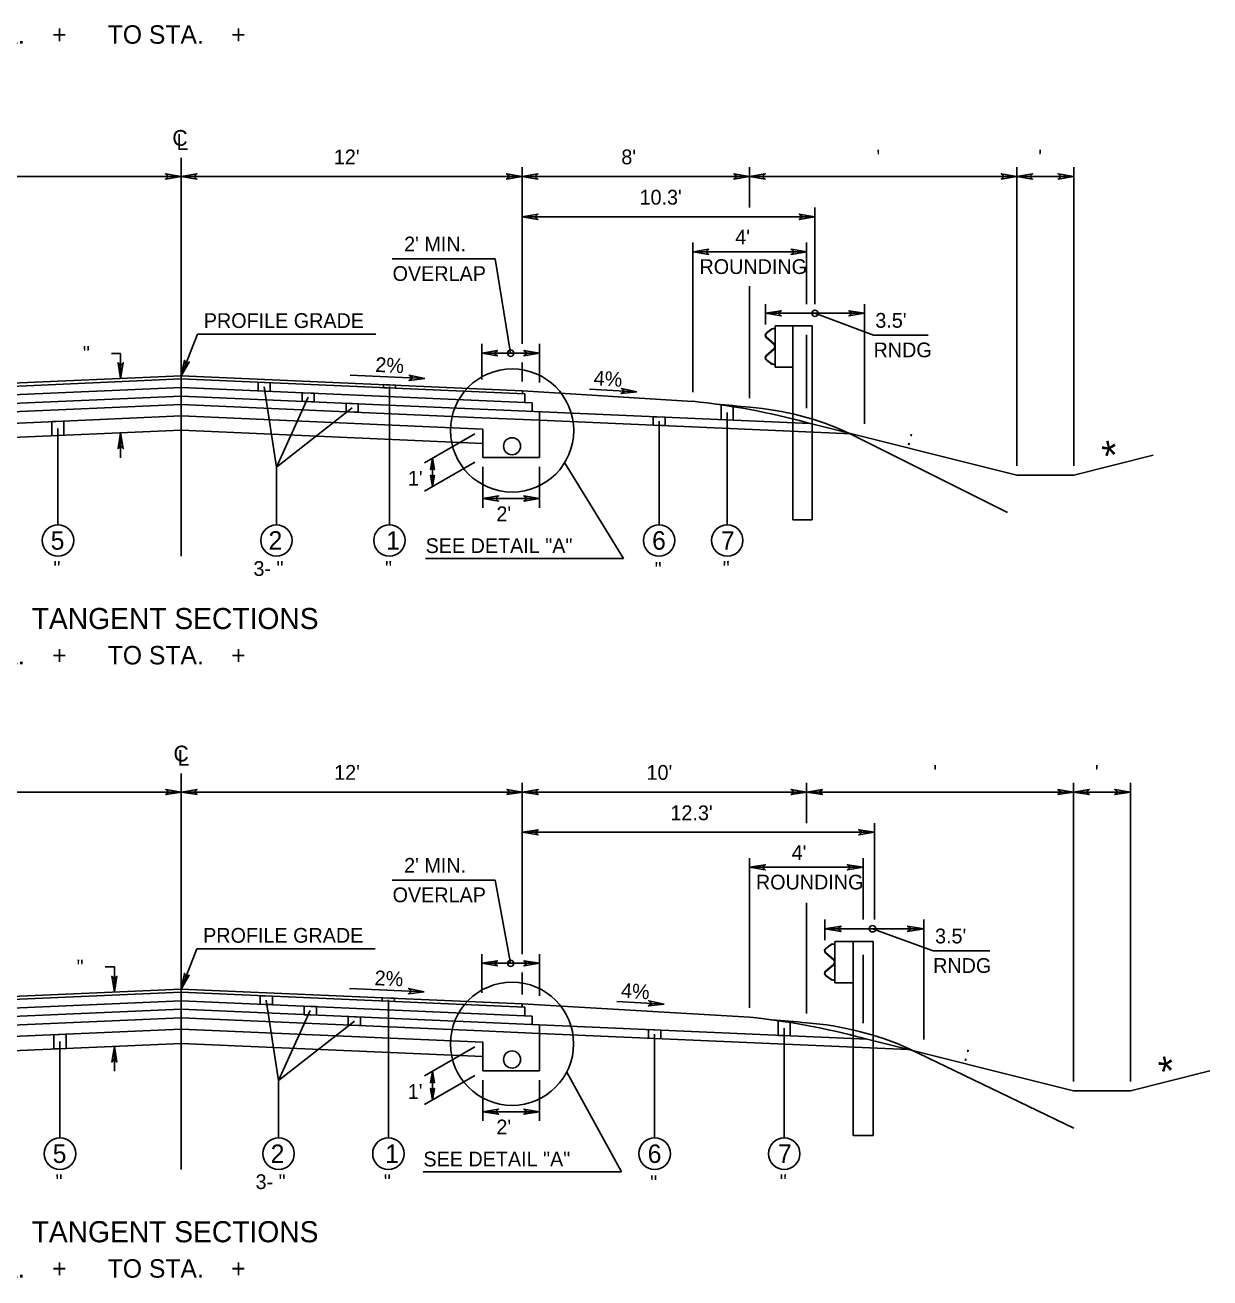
# Model space of a CAD drawing. Extents: x -540 to 1231, y -564 to 421.
# Drawn here: x 268.9 to 381.2, y 58.8 to 177.6 of the extents above; entities that cross this region are included whole.
import ezdxf

# ---------------------------------------------------------------- set-up
doc = ezdxf.new("R2010")
doc.units = 0
doc.layers.add('1', color=7, linetype='Continuous')
doc.layers.add('Des_ Drain_ Ftrs', color=7, linetype='Continuous')

msp = doc.modelspace()

# ---------------------------------------------------------------- linework, layer by layer
at = {"layer": '1'}
for p, q in [((283.71, 127.24), (283.71, 165)), ((316.04, 147.36), (316.04, 164.12)), ((337.59, 160.3), (337.59, 164.12)), ((362.93, 135.79), (362.93, 164.12)), ((368.32, 135.79), (368.32, 164.12)), ((283.71, 163.24), (251.38, 163.24)), ((283.71, 163.24), (316.04, 163.24)), ((316.04, 163.24), (337.59, 163.24)), ((337.59, 163.24), (362.93, 163.24)), ((362.93, 163.24), (368.32, 163.24)), ((316.04, 159.42), (343.79, 159.42)), ((343.79, 151.14), (343.79, 160.3)), ((332.21, 142.79), (332.21, 156.97)), ((342.98, 151.14), (342.98, 156.97)), ((332.23, 156.09), (343.01, 156.09)), ((303.72, 155.43), (313.48, 155.43)), ((314.94, 146.48), (313.48, 155.43)), ((337.59, 142.23), (337.59, 152.82)), ((339.1, 149.19), (339.1, 151.14)), ((348.48, 139.78), (348.48, 151.14)), ((339.1, 150.26), (348.48, 150.26)), ((343.79, 150.26), (349.35, 148.19)), ((339.7, 148.8), (339.18, 148.41)), ((339.71, 148.77), (339.2, 148.38)), ((340.01, 148.85), (339.7, 148.8)), ((340.01, 148.82), (339.71, 148.77)), ((340.01, 149.08), (340.01, 145.15)), ((340.01, 149.08), (341.7, 149.08)), ((341.7, 149.08), (341.7, 130.68)), ((343.52, 149.08), (341.7, 149.08)), ((343.52, 149.08), (343.52, 130.68)), ((283.71, 144.34), (285.24, 148.29)), ((302.15, 148.29), (285.24, 148.29)), ((312.2, 143.97), (312.2, 147.36)), ((317.68, 143.7), (317.68, 147.36)), ((339.17, 147.97), (339.9, 147.34)), ((339.19, 148), (339.92, 147.36)), ((342.98, 141.27), (342.98, 148.22)), ((349.35, 148.19), (354.51, 148.19)), ((277.97, 146.45), (277.09, 146.45)), ((277.97, 146.45), (277.97, 144.09)), ((312.2, 146.48), (317.68, 146.48)), ((339.9, 146.89), (339.17, 146.25)), ((339.92, 146.87), (339.19, 146.23)), ((339.98, 147.15), (339.98, 147.08)), ((340.01, 147.15), (340.01, 147.08)), ((316.04, 143.8), (316.04, 145.6)), ((339.18, 145.82), (339.7, 145.43)), ((339.2, 145.84), (339.71, 145.46)), ((339.7, 145.43), (340.01, 145.38)), ((339.71, 145.46), (340.01, 145.41)), ((340.01, 145.15), (341.7, 145.15)), ((251.14, 142.61), (283.71, 144.04)), ((251.38, 142.92), (283.71, 144.34)), ((316.05, 142.92), (283.71, 144.34)), ((316.28, 142.61), (283.71, 144.04)), ((299.73, 144.39), (306.81, 144.08)), ((250.44, 141.77), (283.71, 143.23)), ((316.99, 141.77), (283.71, 143.23)), ((291.57, 143.29), (292.74, 135.66)), ((303.45, 143.31), (303.45, 130.21)), ((316.05, 142.62), (316.05, 142.92)), ((332.21, 141.91), (316.05, 142.92)), ((316.28, 142.61), (316.28, 141.8)), ((326.91, 142.81), (322.42, 143.07)), ((224.11, 139.82), (283.71, 142.42)), ((255.22, 140.36), (283.71, 141.61)), ((343.32, 139.82), (283.71, 142.42)), ((312.2, 140.36), (283.71, 141.61)), ((295.75, 142.3), (292.74, 135.66)), ((316.98, 141.77), (316.98, 140.96)), ((255.12, 139.28), (283.71, 140.53)), ((312.3, 139.28), (283.71, 140.53)), ((299.93, 141.29), (292.74, 135.66)), ((317.69, 140.13), (312.2, 140.36)), ((317.69, 140.93), (317.69, 140.13)), ((335.47, 140.86), (335.47, 130.21)), ((339.1, 141.13), (339.1, 141.13)), ((255.12, 137.93), (283.71, 139.18)), ((272.03, 139.35), (272.03, 130.21)), ((312.3, 137.93), (283.71, 139.18)), ((312.3, 136.59), (312.3, 139.28)), ((312.3, 139.28), (312.3, 139.28)), ((317.69, 136.59), (317.69, 140.13)), ((347.25, 138.83), (317.69, 140.13)), ((329.01, 140.04), (329.01, 130.21)), ((342.98, 139.9), (362.93, 134.91)), ((277.97, 138.93), (277.97, 136.56)), ((311.54, 138.84), (306.78, 136.09)), ((346.99, 138.9), (362.04, 131.37)), ((375.85, 136.8), (368.32, 134.91)), ((375.85, 136.8), (368.32, 134.91)), ((292.74, 135.66), (292.74, 130.21)), ((311.54, 136.15), (306.77, 133.39)), ((307.54, 136.53), (307.52, 133.83)), ((312.3, 136.59), (317.69, 136.59)), ((312.3, 135.71), (312.3, 131.82)), ((317.69, 135.71), (317.69, 131.82)), ((320.06, 136.1), (325.65, 127.02)), ((362.93, 134.91), (368.32, 134.91)), ((312.3, 132.7), (317.69, 132.7)), ((343.52, 130.68), (341.7, 130.68)), ((306.87, 127.02), (325.65, 127.02)), ((283.71, 69.09), (283.71, 106.63)), ((316.04, 89.51), (316.04, 105.75)), ((342.98, 101.93), (342.98, 105.75)), ((368.3, 77.41), (368.3, 105.75)), ((373.69, 77.41), (373.69, 105.75)), ((283.74, 104.87), (251.41, 104.87)), ((283.74, 104.87), (316.07, 104.87)), ((316.07, 104.87), (343.01, 104.87)), ((343.01, 104.87), (368.3, 104.87)), ((368.3, 104.87), (373.69, 104.87)), ((316.05, 101.05), (349.42, 101.05)), ((349.42, 92.78), (349.42, 101.93)), ((337.59, 84.41), (337.59, 98.61)), ((348.37, 92.78), (348.37, 98.61)), ((337.58, 97.73), (348.36, 97.73)), ((303.71, 96.52), (313.48, 96.52)), ((314.94, 88.63), (313.48, 96.52)), ((342.98, 83.87), (342.98, 94.36)), ((344.72, 90.83), (344.72, 92.78)), ((354.11, 81.41), (354.11, 92.78)), ((344.72, 91.9), (354.11, 91.9)), ((349.24, 91.9), (355, 89.82)), ((345.34, 90.43), (344.81, 90.04)), ((345.36, 90.4), (344.83, 90.02)), ((345.67, 90.48), (345.34, 90.43)), ((345.67, 90.45), (345.36, 90.4)), ((345.67, 90.71), (345.67, 86.78)), ((345.67, 90.71), (347.42, 90.71)), ((347.42, 90.71), (347.42, 72.31)), ((349.31, 90.71), (347.42, 90.71)), ((349.31, 90.71), (349.31, 72.31)), ((283.71, 86.19), (285.18, 90)), ((302.09, 90), (285.18, 90)), ((312.2, 85.83), (312.2, 89.51)), ((317.68, 85.56), (317.68, 89.51)), ((344.79, 89.61), (345.55, 88.97)), ((344.81, 89.63), (345.57, 88.99)), ((348.37, 82.96), (348.37, 89.42)), ((355, 89.82), (360.35, 89.82)), ((277.38, 88.28), (276.5, 88.28)), ((277.38, 88.28), (277.38, 85.91)), ((312.2, 88.63), (317.68, 88.63)), ((345.55, 88.52), (344.79, 87.89)), ((345.57, 88.5), (344.81, 87.86)), ((345.64, 88.78), (345.64, 88.71)), ((345.67, 88.78), (345.67, 88.71)), ((316.04, 85.66), (316.04, 87.75)), ((344.81, 87.45), (345.34, 87.06)), ((344.83, 87.48), (345.36, 87.09)), ((345.34, 87.06), (345.67, 87.01)), ((345.36, 87.09), (345.67, 87.04)), ((345.67, 86.78), (347.42, 86.78)), ((251.14, 84.47), (283.71, 85.89)), ((251.38, 84.78), (283.71, 86.19)), ((316.04, 84.78), (283.71, 86.19)), ((316.28, 84.47), (283.71, 85.89)), ((299.66, 86.24), (306.75, 85.93)), ((250.43, 83.63), (283.71, 85.08)), ((316.99, 83.63), (283.71, 85.08)), ((291.78, 85.13), (292.94, 77.51)), ((303.35, 85.18), (303.35, 72.06)), ((316.04, 84.48), (316.04, 84.78)), ((337.59, 83.53), (316.04, 84.78)), ((316.28, 84.47), (316.28, 83.65)), ((329.5, 84.75), (325.01, 85.01)), ((218.73, 81.44), (283.71, 84.27)), ((255.22, 82.22), (283.71, 83.46)), ((348.69, 81.44), (283.71, 84.27)), ((312.2, 82.22), (283.71, 83.46)), ((295.95, 84.15), (292.94, 77.51)), ((316.99, 83.63), (316.99, 82.82)), ((255.12, 81.14), (283.71, 82.39)), ((312.3, 81.14), (283.71, 82.39)), ((300.13, 83.14), (292.94, 77.51)), ((317.69, 81.98), (312.2, 82.22)), ((317.69, 82.79), (317.69, 81.98)), ((317.69, 78.44), (317.69, 81.98)), ((352.62, 80.45), (317.69, 81.98)), ((340.87, 82.47), (340.87, 72.06)), ((344.72, 82.77), (344.72, 82.77)), ((255.12, 79.79), (283.71, 81.04)), ((272.22, 81.21), (272.22, 72.06)), ((312.3, 79.79), (283.71, 81.04)), ((312.3, 78.44), (312.3, 81.14)), ((312.3, 81.14), (312.3, 81.14)), ((317.69, 81.83), (317.69, 81.83)), ((328.59, 81.91), (328.59, 72.06)), ((348.37, 81.52), (368.3, 76.53)), ((277.38, 80.76), (277.38, 78.39)), ((311.54, 80.7), (306.78, 77.95)), ((352.73, 80.53), (368.34, 73.01)), ((312.3, 78.44), (317.69, 78.44)), ((381.23, 78.42), (373.69, 76.53)), ((292.94, 77.51), (292.94, 72.06)), ((311.54, 78), (306.76, 75.25)), ((307.54, 78.39), (307.52, 75.68)), ((312.3, 77.56), (312.3, 73.68)), ((317.69, 77.56), (317.69, 73.68)), ((320.25, 78.3), (325.45, 68.87)), ((368.3, 76.53), (373.69, 76.53)), ((312.3, 74.56), (317.69, 74.56)), ((349.31, 72.31), (347.42, 72.31)), ((306.66, 68.87), (325.45, 68.87))]:
    msp.add_line(p, q, dxfattribs=at)
for points in [[(291, 143.72), (292.15, 143.67), (292.15, 142.86), (291, 142.91)], [(295.18, 142.73), (296.32, 142.68), (296.32, 141.87), (295.18, 141.92)], [(302.88, 143.5), (304.03, 143.45), (304.03, 143.15), (302.88, 143.2)], [(299.35, 141.73), (300.5, 141.68), (300.5, 140.88), (299.35, 140.93)], [(334.89, 141.58), (336.04, 141.4), (336.04, 140.13), (334.89, 140.18)], [(328.44, 140.46), (329.58, 140.41), (329.58, 139.61), (328.44, 139.66)], [(271.46, 139.99), (272.6, 140.04), (272.6, 138.7), (271.46, 138.65)], [(291.2, 85.56), (292.35, 85.51), (292.35, 84.71), (291.2, 84.76)], [(295.38, 84.57), (296.53, 84.52), (296.53, 83.71), (295.38, 83.76)], [(302.77, 85.36), (303.92, 85.31), (303.92, 85.01), (302.77, 85.06)], [(299.55, 83.58), (300.7, 83.53), (300.7, 82.72), (299.55, 82.77)], [(340.3, 83.19), (341.44, 83.02), (341.44, 81.75), (340.3, 81.8)], [(328.02, 82.34), (329.17, 82.29), (329.17, 81.48), (328.02, 81.53)], [(271.65, 81.86), (272.8, 81.91), (272.8, 80.56), (271.65, 80.51)]]:
    msp.add_lwpolyline(points, close=True, dxfattribs=at)
for centre, radius in [((343.79, 150.26), 0.3), ((314.94, 146.48), 0.3), ((315.08, 139.15), 5.84), ((315.07, 137.66), 0.808), ((272.03, 128.72), 1.49), ((292.74, 128.72), 1.49), ((303.45, 128.72), 1.49), ((329.01, 128.72), 1.49), ((335.47, 128.72), 1.49), ((314.94, 88.63), 0.3), ((315.07, 81), 5.84), ((315.07, 79.51), 0.808), ((272.22, 70.58), 1.49), ((292.94, 70.58), 1.49), ((303.35, 70.58), 1.49), ((328.59, 70.58), 1.49), ((340.87, 70.58), 1.49)]:
    msp.add_circle(centre, radius, dxfattribs=at)
for centre, radius, start, end in [((339.35, 148.18), 0.278, 126.9799, 229.021), ((339.35, 148.18), 0.249, 126.9799, 229.021), ((339.74, 147.15), 0.249, 0, 49.0365), ((339.74, 147.15), 0.278, 0, 49.0365), ((339.35, 146.04), 0.278, 130.979, 233.0201), ((339.35, 146.04), 0.249, 130.979, 233.0201), ((339.74, 147.08), 0.249, 310.9635, 0), ((339.74, 147.08), 0.278, 310.9635, 0), ((325.32, 75.08), 67.19, 74.7619, 84.1205), ((326.78, 40.69), 101.24, 83.8633, 85.6775), ((335.48, 114.07), 27.37, 65.1374, 85.5513), ((330.71, 16.69), 67.19, 74.7598, 84.1183)]:
    msp.add_arc(centre, radius, start, end, dxfattribs=at)
msp.add_ellipse((349.24, 91.9), major_axis=(-0.311, 0), ratio=0.964041, dxfattribs=at)
for centre, major_axis, start_param, end_param in [((344.98, 89.82), (-0.288, 0), 5.35781, 7.138763), ((344.98, 89.82), (-0.258, 0), 5.35781, 7.138763), ((345.38, 88.78), (0.258, 0), 0, 0.855848), ((345.38, 88.71), (0.258, 0), 5.427337, 6.283185), ((345.38, 88.78), (0.288, 0), 0, 0.855848), ((345.38, 88.71), (0.288, 0), 5.427337, 6.283185), ((344.98, 87.68), (-0.288, 0), 5.427608, 7.208561), ((344.98, 87.68), (-0.258, 0), 5.427608, 7.208561), ((331.77, -17.68), (105.02, 0), 1.463691, 1.495354), ((340.79, 55.7), (28.39, 0), 1.136862, 1.493152)]:
    msp.add_ellipse(centre, major_axis=major_axis, ratio=0.964041, start_param=start_param, end_param=end_param, dxfattribs=at)
at = {"layer": 'Des_ Drain_ Ftrs'}
for points in [[(283.71, 163.24), (282.22, 162.99), (282.52, 163.24), (282.22, 163.49)], [(283.71, 163.24), (285.2, 162.99), (284.91, 163.24), (285.2, 163.49)], [(316.04, 163.24), (314.55, 162.99), (314.85, 163.24), (314.55, 163.49)], [(316.04, 163.24), (317.53, 162.99), (317.23, 163.24), (317.53, 163.49)], [(337.59, 163.24), (336.11, 162.99), (336.4, 163.24), (336.11, 163.49)], [(337.59, 163.24), (339.08, 162.99), (338.79, 163.24), (339.08, 163.49)], [(362.93, 163.24), (361.44, 162.99), (361.73, 163.24), (361.44, 163.49)], [(362.93, 163.24), (364.42, 162.99), (364.12, 163.24), (364.42, 163.49)], [(368.32, 163.24), (366.83, 162.99), (367.12, 163.24), (366.83, 163.49)], [(316.04, 159.42), (317.53, 159.17), (317.24, 159.42), (317.53, 159.67)], [(343.79, 159.42), (342.3, 159.17), (342.6, 159.42), (342.3, 159.67)], [(332.23, 156.09), (333.72, 155.85), (333.43, 156.09), (333.72, 156.34)], [(343.01, 156.09), (341.52, 155.85), (341.82, 156.09), (341.52, 156.34)], [(339.1, 150.26), (340.59, 150.01), (340.29, 150.26), (340.59, 150.51)], [(348.48, 150.26), (347, 150.01), (347.29, 150.26), (347, 150.51)], [(312.2, 146.48), (313.69, 146.23), (313.39, 146.48), (313.69, 146.73)], [(317.68, 146.48), (316.2, 146.23), (316.49, 146.48), (316.2, 146.73)], [(277.97, 144.09), (278.22, 145.57), (277.97, 145.28), (277.72, 145.57)], [(283.71, 144.34), (284.48, 145.64), (284.14, 145.45), (284.01, 145.81)], [(306.81, 144.08), (305.31, 143.9), (305.62, 144.13), (305.33, 144.39)], [(326.91, 142.81), (325.41, 142.65), (325.72, 142.88), (325.44, 143.14)], [(277.97, 138.93), (278.22, 137.44), (277.97, 137.74), (277.72, 137.44)], [(307.54, 136.53), (307.35, 135.45), (307.54, 135.66), (307.72, 135.45)], [(307.52, 133.83), (307.35, 134.91), (307.53, 134.7), (307.71, 134.91)], [(312.3, 132.7), (313.79, 132.45), (313.49, 132.7), (313.79, 132.95)], [(317.69, 132.7), (316.2, 132.45), (316.5, 132.7), (316.2, 132.95)], [(283.74, 104.87), (282.25, 104.63), (282.54, 104.87), (282.25, 105.12)], [(283.74, 104.87), (285.22, 104.63), (284.93, 104.87), (285.22, 105.12)], [(316.07, 104.87), (314.58, 104.63), (314.87, 104.87), (314.58, 105.12)], [(316.07, 104.87), (317.55, 104.63), (317.26, 104.87), (317.55, 105.12)], [(343.01, 104.87), (341.52, 104.63), (341.81, 104.87), (341.52, 105.12)], [(343.01, 104.87), (344.5, 104.63), (344.2, 104.87), (344.5, 105.12)], [(368.3, 104.87), (366.82, 104.63), (367.11, 104.87), (366.82, 105.12)], [(368.3, 104.87), (369.79, 104.63), (369.5, 104.87), (369.79, 105.12)], [(373.69, 104.87), (372.2, 104.63), (372.5, 104.87), (372.2, 105.12)], [(316.05, 101.05), (317.54, 100.8), (317.24, 101.05), (317.54, 101.3)], [(349.42, 101.05), (347.93, 100.8), (348.22, 101.05), (347.93, 101.3)], [(337.58, 97.73), (339.07, 97.48), (338.78, 97.73), (339.07, 97.97)], [(348.36, 97.73), (346.87, 97.48), (347.17, 97.73), (346.87, 97.97)], [(344.72, 91.9), (346.27, 91.65), (345.96, 91.9), (346.27, 92.14)], [(354.11, 91.9), (352.56, 91.65), (352.87, 91.9), (352.56, 92.14)], [(312.2, 88.63), (313.68, 88.38), (313.39, 88.63), (313.68, 88.88)], [(317.68, 88.63), (316.19, 88.38), (316.49, 88.63), (316.19, 88.88)], [(277.38, 85.91), (277.62, 87.4), (277.38, 87.11), (277.13, 87.4)], [(283.71, 86.19), (284.47, 87.49), (284.14, 87.31), (284.01, 87.67)], [(306.75, 85.93), (305.25, 85.75), (305.55, 85.98), (305.27, 86.25)], [(329.5, 84.75), (328, 84.59), (328.31, 84.82), (328.03, 85.08)], [(277.38, 80.76), (277.62, 79.27), (277.38, 79.57), (277.13, 79.27)], [(307.54, 78.39), (307.35, 77.31), (307.53, 77.52), (307.71, 77.3)], [(307.52, 75.68), (307.35, 76.77), (307.53, 76.55), (307.71, 76.77)], [(312.3, 74.56), (313.79, 74.31), (313.49, 74.56), (313.79, 74.8)], [(317.69, 74.56), (316.2, 74.31), (316.49, 74.56), (316.2, 74.8)]]:
    msp.add_lwpolyline(points, close=True, dxfattribs=at)

# ---------------------------------------------------------------- texts
at = {"layer": '1'}
for s, height, p in [('STA.    +      TO STA.    +     ', 1.75, (263.68, 175.82)), ("12'", 1.4, (298.18, 164.39)), ("8'", 1.4, (325.43, 164.39)), ("  '", 1.4, (348.57, 164.39)), (" '", 1.4, (364.43, 164.39)), ("10.3'", 1.4, (327.16, 160.57)), ("4'", 1.4, (336.23, 156.79)), ("2' MIN.", 1.4, (304.84, 156.13)), ('OVERLAP', 1.4, (303.75, 153.33)), ('ROUNDING', 1.4, (332.84, 153.99)), ('PROFILE GRADE', 1.4, (285.85, 148.87)), ("3.5'", 1.4, (349.51, 148.89)), ('RNDG', 1.4, (349.34, 146.09)), ("2'", 1.4, (313.59, 130.55)), ('5', 1.75, (271.34, 127.85)), ('2', 1.75, (291.99, 127.85)), ('1', 1.75, (303.15, 127.85)), ('6', 1.75, (328.35, 127.85)), ('7', 1.75, (334.88, 127.85)), ('SEE DETAIL "A"', 1.4, (306.88, 127.53)), (' "', 1.4, (271.08, 125.36)), ('3- "', 1.4, (290.56, 125.36)), (' "', 1.4, (302.51, 125.36)), (' "', 1.4, (328.07, 125.27)), (' "', 1.4, (334.52, 125.36)), ('TANGENT SECTIONS', 2, (269.54, 120.32)), ('STA.    +      TO STA.    +     ', 1.75, (263.68, 116.97)), ("12'", 1.4, (298.21, 106.03)), ("10'", 1.4, (327.82, 106.03)), ("  '", 1.4, (353.96, 106.03)), (" '", 1.4, (369.8, 106.03)), ("12.3'", 1.4, (330.09, 102.2)), ("4'", 1.4, (341.58, 98.43)), ("2' MIN.", 1.4, (304.84, 97.22)), ('ROUNDING', 1.4, (338.19, 95.63)), ('OVERLAP', 1.4, (303.75, 94.42)), ('PROFILE GRADE', 1.4, (285.79, 90.58)), ("3.5'", 1.4, (355.17, 90.52)), ('RNDG', 1.4, (354.99, 87.72)), ("2'", 1.4, (313.59, 72.41)), ('5', 1.75, (271.53, 69.7)), ('2', 1.75, (292.19, 69.7)), ('1', 1.75, (303.05, 69.7)), ('6', 1.75, (327.93, 69.7)), ('7', 1.75, (340.28, 69.7)), ('SEE DETAIL "A"', 1.4, (306.67, 69.37)), (' "', 1.4, (271.28, 67.22)), ('3- "', 1.4, (290.76, 67.22)), (' "', 1.4, (302.4, 67.22)), (' "', 1.4, (327.65, 67.12)), (' "', 1.4, (339.93, 67.22)), ('TANGENT SECTIONS', 2, (269.53, 62.18)), ('STA.    +      TO STA.    +     ', 1.75, (263.68, 58.82))]:
    msp.add_text(s, height=height, dxfattribs=at).set_placement(p)
for s, height, rotation, p in [('  "', 1.4, 0.1438, (273.35, 145.75)), ('2%', 1.4, 357.3732, (302.09, 144.71)), ('4%', 1.4, 356.3472, (322.78, 143.45)), (' : ', 1.4, 345.7718, (351.91, 137.96)), ('*', 2.8, 12.8479, (371.41, 135.27)), ("1'", 1.4, 0.1438, (305.2, 133.92)), ('  "', 1.4, 0.1438, (272.76, 87.58)), ('2%', 1.4, 357.3731, (302.02, 86.56)), ('4%', 1.4, 356.3924, (325.37, 85.38)), (' : ', 1.4, 345.7718, (357.29, 79.58)), ('*', 2.8, 12.8479, (376.78, 76.89)), ("1'", 1.4, 0.1438, (305.19, 75.77))]:
    msp.add_text(s, height=height, rotation=rotation, dxfattribs=at).set_placement(p)
at = {"layer": 'Des_ Drain_ Ftrs'}
for s, p in [('C', (282.87, 166.14)), ('L', (283.26, 165.75)), ('C', (282.98, 107.77)), ('L', (283.37, 107.37))]:
    msp.add_text(s, height=1.5, dxfattribs=at).set_placement(p)

doc.saveas('drawing.dxf')
